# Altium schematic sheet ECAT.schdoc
size 297 x 209 mm; Symbol: Drawing-Symbol_A4; Company: 嘉立创EDA; Version: V1.0; Page Size: A4; @Project Name: 西柚在学EtherCAT; @Update Date: 2026-07-29; @Create Date: 2026-07-29; Device: Drawing-Symbol_A4; @Board Name: HPM5E3YIVK1; @Page Name: P4; @Create Time: 01:19:16; @Page Count: 4; @Page No: 4; @Schematic Name: HPM5E3YIVK1; @Update Time: 01:19:16; @Assembly Variant: Basic; Border: 1; Title Block Position: 3; Size: A4; Width: 1170; Height: 825; Region Start: 1; X Region Count: 6; Y Region Count: 4; Blade Width: 10
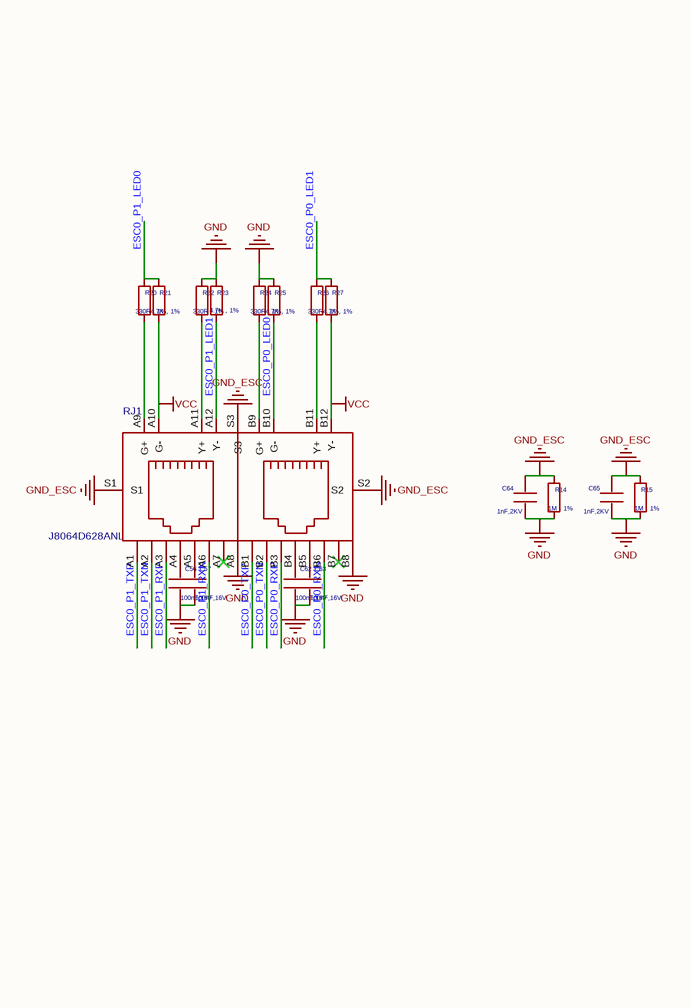
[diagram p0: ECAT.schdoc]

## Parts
C56  value 100nF,16V  [03_HPM_Capacitance:C_0402_1005Metric]
C57  value 100nF,16V  [03_HPM_Capacitance:C_0402_1005Metric]
C62  value 100nF,16V  [03_HPM_Capacitance:C_0402_1005Metric]
C63  value 100nF,16V  [03_HPM_Capacitance:C_0402_1005Metric]
C64  value 1nF,2KV  [03_HPM_Capacitance:C_1206_3216Metric]
C65  value 1nF,2KV  [03_HPM_Capacitance:C_1206_3216Metric]
R14  value 1M，1%  [02_HPM_Resistor:R_1206_3216Metric]
R15  value 1M，1%  [02_HPM_Resistor:R_1206_3216Metric]
R20  value 330R，1%  [02_HPM_Resistor:R_0402_1005Metric]
R21  value 4.7K，1%  [02_HPM_Resistor:R_0402_1005Metric]
R22  value 330R，1%  [02_HPM_Resistor:R_0402_1005Metric]
R23  value 4.7K，1%  [02_HPM_Resistor:R_0402_1005Metric]
R24  value 330R，1%  [02_HPM_Resistor:R_0402_1005Metric]
R25  value 4.7K，1%  [02_HPM_Resistor:R_0402_1005Metric]
R26  value 330R，1%  [02_HPM_Resistor:R_0402_1005Metric]
R27  value 4.7K，1%  [02_HPM_Resistor:R_0402_1005Metric]
RJ1  J8064D628ANL  [RJ45-TH_J8064D628ANL]

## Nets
GND: C56.2 C57.2 C62.2 C63.2 C64.2 C65.2 R14.1 R15.1 R22.2 R23.2 R24.2 R25.2 RJ1.A8 RJ1.B8
GND_ESC: C64.1 C65.1 R14.2 R15.2 RJ1.S1 RJ1.S2 RJ1.S3
VCC: R21.1 R27.1 RJ1.A10(G-) RJ1.B12(Y-)
ESC0_P0_LED0: R25.1 RJ1.B10(G-)
ESC0_P0_LED1: R26.2 R27.2
ESC0_P0_RXN: RJ1.B6
ESC0_P0_RXP: RJ1.B3
ESC0_P0_TXN: RJ1.B2
ESC0_P0_TXP: RJ1.B1
ESC0_P1_LED0: R20.2 R21.2
ESC0_P1_LED1: R23.1 RJ1.A12(Y-)
ESC0_P1_RXN: RJ1.A6
ESC0_P1_RXP: RJ1.A3
ESC0_P1_TXN: RJ1.A2
ESC0_P1_TXP: RJ1.A1
NetC56_1: C56.1 RJ1.A4
NetC57_1: C57.1 RJ1.A5
NetC62_1: C62.1 RJ1.B4
NetC63_1: C63.1 RJ1.B5
NetR20_1: R20.1 RJ1.A9(G+)
NetR22_1: R22.1 RJ1.A11(Y+)
NetR24_1: R24.1 RJ1.B9(G+)
NetR26_1: R26.1 RJ1.B11(Y+)

Not connected (* = marked no-connect by the designer): RJ1 A7* B7*

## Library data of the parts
C56 = 电容0402: Model: CL05B104KO5NNNC; Company: SAMSUNG(三星); ki_keywords: cap capacitor; ki_description: 0402; ki_fp_filters: C_*; ID: $1I27; 3D Model: 222a10e09e6e477a9f85628e277082cb0819f05c4eef4c71ace90d822a990e87; 3D Model Transform: 39.37,19.685,19.685,0,0,0,0,0,0; AddInBom: yes; UniqueId: gge1051; ModelName: C0402
C57 = 电容0402: Model: CL05B104KO5NNNC; Company: SAMSUNG(三星); ki_keywords: cap capacitor; ki_description: 0402; ki_fp_filters: C_*; ID: $1I27; 3D Model: 222a10e09e6e477a9f85628e277082cb0819f05c4eef4c71ace90d822a990e87; 3D Model Transform: 39.37,19.685,19.685,0,0,0,0,0,0; AddInBom: yes; UniqueId: gge1052; ModelName: C0402
C62 = 电容0402: Model: CL05B104KO5NNNC; Company: SAMSUNG(三星); ki_keywords: cap capacitor; ki_description: 0402; ki_fp_filters: C_*; ID: $1I27; 3D Model: 222a10e09e6e477a9f85628e277082cb0819f05c4eef4c71ace90d822a990e87; 3D Model Transform: 39.37,19.685,19.685,0,0,0,0,0,0; AddInBom: yes; UniqueId: b3e980a047527b8f_44; ModelName: C0402
C63 = 电容0402: Model: CL05B104KO5NNNC; Company: SAMSUNG(三星); ki_keywords: cap capacitor; ki_description: 0402; ki_fp_filters: C_*; ID: $1I27; 3D Model: 222a10e09e6e477a9f85628e277082cb0819f05c4eef4c71ace90d822a990e87; 3D Model Transform: 39.37,19.685,19.685,0,0,0,0,0,0; AddInBom: yes; UniqueId: b3e980a047527b8f_45; ModelName: C0402
C64 = 电容1206: Model: 1206B102K202NT; Company: FH(风华); AddInBom: yes; ki_keywords: cap capacitor; ki_description: 1206; ki_fp_filters: C_*; UniqueId: gge1034; ID: $4I70; ModelId: e4be705b945545a48e666415e3682bd80819f05c4eef4c71ace90d822a990e87; ModelName: C1206_L3.2-W1.6-H1.3; ModelTransform: 125.98400187730789,62.992000938653945,51.1809981226921,0,0,0,0,0,0
C65 = 电容1206: Model: 1206B102K202NT; Company: FH(风华); AddInBom: yes; ki_keywords: cap capacitor; ki_description: 1206; ki_fp_filters: C_*; UniqueId: gge1035; ID: $4I70; ModelId: e4be705b945545a48e666415e3682bd80819f05c4eef4c71ace90d822a990e87; ModelName: C1206_L3.2-W1.6-H1.3; ModelTransform: 125.98400187730789,62.992000938653945,51.1809981226921,0,0,0,0,0,0
R14 = 电阻1206: Model: ARG06BTC1004; Company: Viking(光颉); AddInBom: yes; ki_keywords: R res resistor; ki_description: Resistor; ki_fp_filters: R_*; UniqueId: gge1043; ID: $4I74; ModelId: 89a1f13db2384da588040e0b3c55bf660819f05c4eef4c71ace90d822a990e87; ModelName: R1206_L3.2-W1.6-H0.6; ModelTransform: 125.98400187730789,62.992000938653945,22.047200093865392,0,0,0,0,0,0
R15 = 电阻1206: Model: ARG06BTC1004; Company: Viking(光颉); AddInBom: yes; ki_keywords: R res resistor; ki_description: Resistor; ki_fp_filters: R_*; UniqueId: gge1033; ID: $4I74; ModelId: 89a1f13db2384da588040e0b3c55bf660819f05c4eef4c71ace90d822a990e87; ModelName: R1206_L3.2-W1.6-H0.6; ModelTransform: 125.98400187730789,62.992000938653945,22.047200093865392,0,0,0,0,0,0
R20 = 电阻0402: Model: 0402WGF1002TCE; Company: UNI-ROYAL(厚声); ki_keywords: R res resistor; ki_description: Resistor; ki_fp_filters: R_*; ID: $3I57; 3D Model: 98c88bc2b9094f218f3a3e30a70127380819f05c4eef4c71ace90d822a990e87; 3D Model Transform: 39.37,19.685,14.173200563192367,0,0,0,0,0,0; AddInBom: yes; UniqueId: gge1053; ModelName: R0402_L1.0-W0.5-H0.4
R21 = 电阻0402: Model: 0402WGF1002TCE; Company: UNI-ROYAL(厚声); ki_keywords: R res resistor; ki_description: Resistor; ki_fp_filters: R_*; ID: $3I57; 3D Model: 98c88bc2b9094f218f3a3e30a70127380819f05c4eef4c71ace90d822a990e87; 3D Model Transform: 39.37,19.685,14.173200563192367,0,0,0,0,0,0; AddInBom: yes; UniqueId: gge1054; ModelName: R0402_L1.0-W0.5-H0.4
R22 = 电阻0402: Model: 0402WGF1002TCE; Company: UNI-ROYAL(厚声); ki_keywords: R res resistor; ki_description: Resistor; ki_fp_filters: R_*; ID: $3I57; 3D Model: 98c88bc2b9094f218f3a3e30a70127380819f05c4eef4c71ace90d822a990e87; 3D Model Transform: 39.37,19.685,14.173200563192367,0,0,0,0,0,0; AddInBom: yes; UniqueId: gge1055; ModelName: R0402_L1.0-W0.5-H0.4
R23 = 电阻0402: Model: 0402WGF1002TCE; Company: UNI-ROYAL(厚声); ki_keywords: R res resistor; ki_description: Resistor; ki_fp_filters: R_*; ID: $3I57; 3D Model: 98c88bc2b9094f218f3a3e30a70127380819f05c4eef4c71ace90d822a990e87; 3D Model Transform: 39.37,19.685,14.173200563192367,0,0,0,0,0,0; AddInBom: yes; UniqueId: gge1056; ModelName: R0402_L1.0-W0.5-H0.4
R24 = 电阻0402: Model: 0402WGF1002TCE; Company: UNI-ROYAL(厚声); ki_keywords: R res resistor; ki_description: Resistor; ki_fp_filters: R_*; ID: $3I57; 3D Model: 98c88bc2b9094f218f3a3e30a70127380819f05c4eef4c71ace90d822a990e87; 3D Model Transform: 39.37,19.685,14.173200563192367,0,0,0,0,0,0; AddInBom: yes; UniqueId: 469542c170a520e3_5; ModelName: R0402_L1.0-W0.5-H0.4
R25 = 电阻0402: Model: 0402WGF1002TCE; Company: UNI-ROYAL(厚声); ki_keywords: R res resistor; ki_description: Resistor; ki_fp_filters: R_*; ID: $3I57; 3D Model: 98c88bc2b9094f218f3a3e30a70127380819f05c4eef4c71ace90d822a990e87; 3D Model Transform: 39.37,19.685,14.173200563192367,0,0,0,0,0,0; AddInBom: yes; UniqueId: 469542c170a520e3_6; ModelName: R0402_L1.0-W0.5-H0.4
R26 = 电阻0402: Model: 0402WGF1002TCE; Company: UNI-ROYAL(厚声); ki_keywords: R res resistor; ki_description: Resistor; ki_fp_filters: R_*; ID: $3I57; 3D Model: 98c88bc2b9094f218f3a3e30a70127380819f05c4eef4c71ace90d822a990e87; 3D Model Transform: 39.37,19.685,14.173200563192367,0,0,0,0,0,0; AddInBom: yes; UniqueId: 469542c170a520e3_7; ModelName: R0402_L1.0-W0.5-H0.4
R27 = 电阻0402: Model: 0402WGF1002TCE; Company: UNI-ROYAL(厚声); ki_keywords: R res resistor; ki_description: Resistor; ki_fp_filters: R_*; ID: $3I57; 3D Model: 98c88bc2b9094f218f3a3e30a70127380819f05c4eef4c71ace90d822a990e87; 3D Model Transform: 39.37,19.685,14.173200563192367,0,0,0,0,0,0; AddInBom: yes; UniqueId: 469542c170a520e3_8; ModelName: R0402_L1.0-W0.5-H0.4
RJ1 = J8064D628ANL: 连接器类型:RJ45插座;安装方式:弯插;端口数量:2;LED:带LED;屏蔽:有屏蔽;触头材质:磷青铜;触头镀层:金;工作温度:0℃~+70℃;; Manufacturer: PULSE(普思); Add into BOM: yes; Connector Type: RJ45插座; Number of Ports: 2; LED: 带LED; Shielding: 有屏蔽; PoE: 不带PoE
